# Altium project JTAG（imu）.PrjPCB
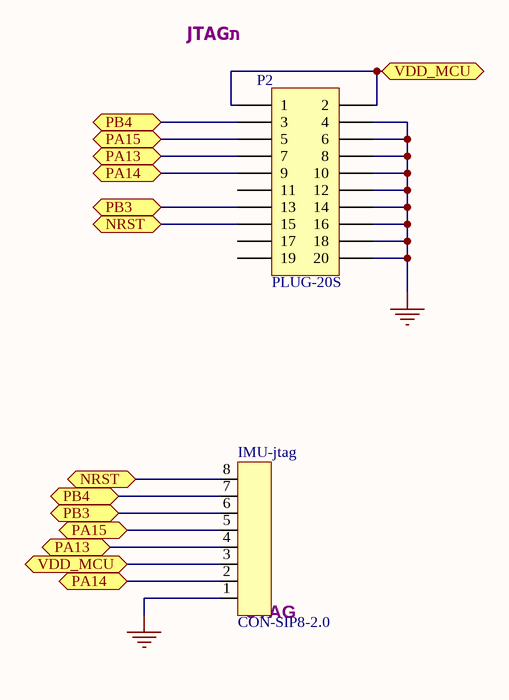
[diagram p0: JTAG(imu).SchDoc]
1 sheet, 2 parts. Net scope: flat (ports and power ports of the same name join across sheets).
Board file: JTAG(imu).PcbDoc

## Sheet JTAG(imu).SchDoc
size A4

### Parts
IMU-jtag  CON-SIP8-2.0  [PLUG1.27-8P]
P2  PLUG-20S  [PLUG-20S]

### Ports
NRST, PA13, PA14, PA15, PB3, PB4, VDD_MCU

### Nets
GND: IMU-jtag.1 P2.4 P2.6 P2.8 P2.10 P2.12 P2.14 P2.16 P2.18 P2.20
NetIMU-jtag_2: IMU-jtag.2 P2.9 ; port PA14
NetIMU-jtag_3: IMU-jtag.3 P2.1 P2.2 ; port VDD_MCU
NetIMU-jtag_4: IMU-jtag.4 P2.7 ; port PA13
NetIMU-jtag_5: IMU-jtag.5 P2.5 ; port PA15
NetIMU-jtag_6: IMU-jtag.6 P2.13 ; port PB3
NetIMU-jtag_7: IMU-jtag.7 P2.3 ; port PB4
NetIMU-jtag_8: IMU-jtag.8 P2.15 ; port NRST

Not connected (* = marked no-connect by the designer): P2 11 17 19

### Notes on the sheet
- JTAGת
- (near IMU-jtag) JTAG

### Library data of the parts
IMU-jtag = CON-SIP8-2.0: 单排针8PIN
P2 = Header 10X2H: Header, 10-Pin, Dual row, Right Angle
